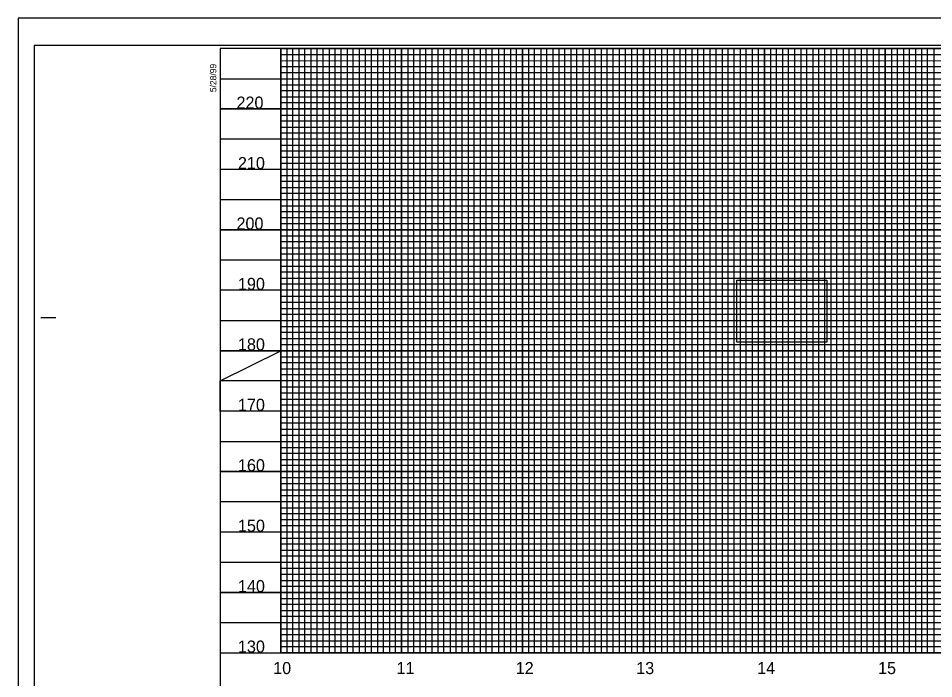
# Model space of a CAD drawing. Extents: x 1779926 to 1781610, y 620464 to 621564.
# Drawn here: x 1779926 to 1780683, y 621018 to 621564 of the extents above; entities that cross this region are included whole.
import ezdxf

# ---------------------------------------------------------------- set-up
doc = ezdxf.new("R2010")
doc.units = 0
for name, color, linetype in [('Exist Vertical Profile Horizontal Axis Label Major', 7, 'Continuous'), ('Exist Vertical Profile Vertical Axis Label', 7, 'Continuous'), ('Prop Grid Mask', 7, 'Continuous'), ('Scratch_Level_0', 7, 'Continuous'), ('Sheet Cutting Line CELL', 7, 'Continuous'), ('Sheet DOT Grid CELL', 7, 'Continuous'), ('Sheet Layout Profile Border Port 1', 7, 'Continuous'), ('Sheet Plot Border Inside CELL', 7, 'Continuous'), ('Sheet Plot Border Outside CELL', 7, 'Continuous'), ('Sheet Profile CELL', 7, 'Continuous'), ('Sheet Profile Grid Major CELL', 7, 'Continuous'), ('Sheet Profile Grid Middle CELL', 7, 'Continuous'), ('Sheet Profile Grid Minor CELL', 7, 'Continuous')]:
    doc.layers.add(name, color=color, linetype=linetype)

msp = doc.modelspace()

# ---------------------------------------------------------------- linework, layer by layer
at = {"layer": 'Prop Grid Mask'}
msp.add_lwpolyline([(1780520.24, 621347.48), (1780594.67, 621347.48), (1780594.67, 621296.16), (1780520.24, 621296.16)], close=True, dxfattribs=at)
at = {"layer": 'Scratch_Level_0'}
msp.add_lwpolyline([(1780142.96, 621039.18), (1780142.96, 621239.19), (1780092.96, 621239.19), (1780092.96, 621264.19), (1780142.96, 621289.19), (1780142.96, 621539.18), (1781392.96, 621539.18), (1781392.96, 621314.18), (1781542.96, 621314.18), (1781542.96, 621039.18)], close=True, dxfattribs=at)
at = {"layer": 'Sheet Cutting Line CELL'}
for p, q in [((1781609.96, 621564.19), (1779925.96, 621564.19)), ((1779925.96, 621564.19), (1779925.96, 620464.19))]:
    msp.add_line(p, q, dxfattribs=at)
at = {"layer": 'Sheet DOT Grid CELL'}
for p, q in [((1780142.96, 621039.19), (1780142.96, 621539.19)), ((1780192.96, 621039.19), (1780192.96, 621539.19)), ((1780242.96, 621039.19), (1780242.96, 621539.19)), ((1780292.96, 621039.19), (1780292.96, 621539.19)), ((1780342.96, 621039.19), (1780342.96, 621539.19)), ((1780392.96, 621039.19), (1780392.96, 621539.19)), ((1780442.96, 621039.19), (1780442.96, 621539.19)), ((1780492.96, 621039.19), (1780492.96, 621539.19)), ((1780542.96, 621039.19), (1780542.96, 621539.19)), ((1780592.96, 621039.19), (1780592.96, 621539.19)), ((1780642.96, 621039.19), (1780642.96, 621539.19)), ((1781392.91, 621489.19), (1780092.96, 621489.19)), ((1781392.91, 621439.19), (1780092.96, 621439.19)), ((1781392.96, 621389.19), (1780092.96, 621389.19)), ((1781392.91, 621339.19), (1780092.96, 621339.19)), ((1781592.96, 621289.19), (1780092.96, 621289.19)), ((1781592.96, 621239.19), (1780092.96, 621239.19)), ((1781592.96, 621189.19), (1780092.96, 621189.19)), ((1781592.96, 621139.19), (1780092.96, 621139.19)), ((1781592.96, 621089.19), (1780092.96, 621089.19))]:
    msp.add_line(p, q, dxfattribs=at)
at = {"layer": 'Sheet Layout Profile Border Port 1'}
msp.add_lwpolyline([(1780142.96, 621378.14), (1780142.96, 621039.19), (1781542.96, 621039.19), (1781542.96, 621314.19)], dxfattribs=at)
at = {"layer": 'Sheet Plot Border Inside CELL'}
msp.add_lwpolyline([(1779938.96, 620486.64), (1781605.46, 620486.64), (1781605.46, 621541.74), (1779938.96, 621541.74)], close=True, dxfattribs=at)
at = {"layer": 'Sheet Plot Border Outside CELL'}
msp.add_lwpolyline([(1779925.96, 620464.19), (1781609.96, 620464.19), (1781609.96, 621564.19), (1779925.96, 621564.19)], close=True, dxfattribs=at)
at = {"layer": 'Sheet Profile CELL'}
for p, q in [((1779944.46, 621316.69), (1779956.96, 621316.69)), ((1780092.96, 621039.19), (1781592.96, 621039.19))]:
    msp.add_line(p, q, dxfattribs=at)
msp.add_lwpolyline([(1781592.96, 621539.19), (1780092.96, 621539.19), (1780092.96, 620489.19), (1781592.96, 620489.19)], close=True, dxfattribs=at)
at = {"layer": 'Sheet Profile Grid Major CELL'}
for points in [[(1780142.96, 621539.19), (1780142.96, 621039.19), (1780192.96, 621039.19), (1780192.96, 621539.19), (1780242.96, 621539.19), (1780242.96, 621039.19), (1780292.96, 621039.19), (1780292.96, 621539.19), (1780342.96, 621539.19), (1780342.96, 621039.19), (1780392.96, 621039.19), (1780392.96, 621539.19), (1780442.96, 621539.19), (1780442.96, 621039.19), (1780492.96, 621039.19), (1780492.96, 621539.19), (1780542.96, 621539.19), (1780542.96, 621039.19), (1780592.96, 621039.19), (1780592.96, 621539.19), (1780642.96, 621539.19), (1780642.96, 621039.19), (1780692.96, 621039.19)], [(1780092.96, 621489.19), (1781392.96, 621489.19)], [(1781392.96, 621439.19), (1780092.96, 621439.19), (1780092.96, 621389.19), (1781392.96, 621389.19)], [(1781392.91, 621339.19), (1780092.96, 621339.19), (1780092.96, 621289.19), (1781592.96, 621289.19)], [(1781592.96, 621239.19), (1780092.96, 621239.19), (1780092.96, 621189.19), (1781592.96, 621189.19)], [(1781592.96, 621139.19), (1780092.96, 621139.19), (1780092.96, 621139.19), (1780092.96, 621089.19), (1781592.96, 621089.19)]]:
    msp.add_lwpolyline(points, dxfattribs=at)
at = {"layer": 'Sheet Profile Grid Middle CELL'}
msp.add_line((1780092.96, 621514.19), (1781392.91, 621514.19), dxfattribs=at)
for points in [[(1780167.96, 621539.19), (1780167.96, 621039.19), (1780217.96, 621039.19), (1780217.96, 621539.19), (1780267.96, 621539.19), (1780267.96, 621039.19), (1780317.96, 621039.19), (1780317.96, 621539.19), (1780367.96, 621539.19), (1780367.96, 621039.19), (1780417.96, 621039.19), (1780417.96, 621539.19), (1780467.96, 621539.19), (1780467.96, 621039.19), (1780517.96, 621039.19), (1780517.96, 621539.19), (1780567.96, 621539.19), (1780567.96, 621039.19), (1780617.96, 621039.19), (1780617.96, 621539.19), (1780667.96, 621539.19), (1780667.96, 621039.19), (1780717.96, 621039.19)], [(1781392.96, 621464.19), (1780092.96, 621464.19), (1780092.96, 621414.19), (1781392.96, 621414.19)], [(1781392.91, 621364.19), (1780092.96, 621364.19), (1780092.96, 621314.19), (1781417.96, 621314.19)], [(1781592.96, 621264.19), (1780092.96, 621264.19), (1780092.96, 621214.19), (1781592.96, 621214.19)], [(1781592.96, 621164.19), (1780092.96, 621164.19), (1780092.96, 621114.19), (1781592.96, 621114.19)], [(1781592.96, 621064.19), (1780092.96, 621064.19)]]:
    msp.add_lwpolyline(points, dxfattribs=at)
at = {"layer": 'Sheet Profile Grid Minor CELL'}
for p, q in [((1780142.96, 621534.19), (1781392.96, 621534.19)), ((1780142.96, 621529.19), (1780142.96, 621529.19)), ((1781392.96, 621529.19), (1780142.96, 621528.84)), ((1780142.96, 621524.19), (1781392.96, 621524.19)), ((1781392.91, 621404.19), (1780142.96, 621404.19)), ((1781392.96, 621399.19), (1780142.96, 621399.19)), ((1781392.96, 621394.19), (1780142.96, 621394.19)), ((1780142.96, 621384.19), (1781392.96, 621384.19)), ((1781392.96, 621379.19), (1780142.96, 621379.19)), ((1780142.96, 621374.19), (1781392.96, 621374.19)), ((1781392.96, 621354.19), (1780142.96, 621354.19)), ((1780142.96, 621349.19), (1781392.96, 621349.19)), ((1781392.91, 621329.19), (1780142.96, 621329.19)), ((1780142.96, 621324.19), (1781392.91, 621324.19)), ((1781542.96, 621304.19), (1780142.96, 621304.19)), ((1780142.96, 621299.19), (1781542.96, 621299.19)), ((1781542.96, 621294.19), (1780142.96, 621294.19)), ((1780142.96, 621284.19), (1781542.96, 621284.19)), ((1781542.96, 621279.19), (1780142.96, 621279.19)), ((1780142.96, 621274.19), (1781542.96, 621274.19)), ((1781542.96, 621269.19), (1780142.96, 621269.19)), ((1780142.96, 621259.19), (1781542.96, 621259.19)), ((1781542.96, 621254.19), (1780142.96, 621254.19)), ((1780142.96, 621249.19), (1781542.96, 621249.19)), ((1781542.96, 621244.19), (1780142.96, 621244.19)), ((1780142.96, 621234.19), (1781542.96, 621234.19)), ((1781542.96, 621229.19), (1780142.96, 621229.19)), ((1780142.96, 621224.19), (1781542.96, 621224.19)), ((1781542.96, 621219.19), (1780142.96, 621219.19)), ((1780142.96, 621209.19), (1781542.96, 621209.19)), ((1781542.96, 621204.19), (1780142.96, 621204.19)), ((1780142.96, 621199.19), (1781542.96, 621199.19)), ((1781542.96, 621194.19), (1780142.96, 621194.19)), ((1780142.96, 621184.19), (1781542.96, 621184.19)), ((1781542.96, 621179.19), (1780142.96, 621179.19)), ((1780142.96, 621174.19), (1781542.96, 621174.19)), ((1781542.96, 621169.19), (1780142.96, 621169.19)), ((1780142.96, 621159.19), (1781542.96, 621159.19)), ((1781542.96, 621154.19), (1780142.96, 621154.19)), ((1781542.96, 621149.19), (1780142.96, 621149.19)), ((1781542.96, 621144.19), (1780142.96, 621144.19)), ((1780142.96, 621134.19), (1781542.96, 621134.19)), ((1781542.96, 621129.19), (1780142.96, 621129.19)), ((1780142.96, 621124.19), (1781542.96, 621124.19)), ((1781542.96, 621119.19), (1780142.96, 621119.19)), ((1780142.96, 621109.19), (1781542.96, 621109.19)), ((1781542.96, 621104.19), (1780142.96, 621104.19)), ((1780142.96, 621099.19), (1781542.96, 621099.19)), ((1781542.96, 621094.19), (1780142.96, 621094.19)), ((1780142.96, 621084.19), (1781542.96, 621084.19)), ((1781542.96, 621079.19), (1780142.96, 621079.19)), ((1780142.96, 621074.19), (1781542.96, 621074.19)), ((1781542.96, 621069.19), (1780142.96, 621069.19)), ((1780142.96, 621059.19), (1781542.96, 621059.19)), ((1781542.96, 621054.19), (1780142.96, 621054.19)), ((1780142.96, 621049.19), (1781542.96, 621049.19))]:
    msp.add_line(p, q, dxfattribs=at)
for points in [[(1780147.96, 621539.19), (1780147.96, 621039.19), (1780152.96, 621039.19), (1780152.96, 621539.19), (1780157.96, 621539.19), (1780157.96, 621039.19), (1780162.96, 621039.19), (1780162.96, 621539.19), (1780172.96, 621539.19), (1780172.96, 621039.19), (1780177.96, 621039.19), (1780177.96, 621539.19), (1780182.96, 621539.19), (1780182.96, 621039.19), (1780187.96, 621039.19), (1780197.96, 621039.19), (1780202.96, 621039.19), (1780202.96, 621539.19), (1780207.96, 621539.19), (1780207.96, 621039.19), (1780212.96, 621039.19), (1780212.96, 621539.19), (1780222.96, 621539.19), (1780222.96, 621039.19), (1780227.96, 621039.19), (1780227.96, 621539.19), (1780232.96, 621539.19), (1780232.96, 621039.19), (1780237.96, 621039.19), (1780237.96, 621539.19), (1780247.96, 621539.19), (1780247.96, 621039.19), (1780252.96, 621039.19), (1780252.96, 621539.19), (1780257.96, 621539.19), (1780257.96, 621039.19), (1780262.96, 621039.19), (1780262.96, 621539.19), (1780272.96, 621539.19), (1780272.96, 621039.19), (1780277.96, 621039.19), (1780277.96, 621539.19), (1780282.96, 621539.19), (1780282.96, 621039.19), (1780287.96, 621039.19), (1780287.96, 621539.19), (1780297.96, 621539.19), (1780297.96, 621039.19), (1780302.96, 621039.19), (1780302.96, 621539.19), (1780307.96, 621539.19), (1780307.96, 621039.19), (1780312.96, 621039.19), (1780312.96, 621539.19), (1780322.96, 621539.19), (1780322.96, 621039.19), (1780327.96, 621039.19), (1780327.96, 621539.19), (1780332.96, 621539.19), (1780332.96, 621039.19), (1780337.96, 621039.19), (1780337.96, 621539.19), (1780347.96, 621539.19), (1780347.96, 621039.19), (1780352.96, 621039.19), (1780352.96, 621539.19), (1780357.96, 621539.19), (1780357.96, 621039.19)], [(1780187.96, 621039.19), (1780187.96, 621539.19), (1780197.96, 621539.19), (1780197.96, 621039.19)], [(1780357.96, 621039.19), (1780362.96, 621039.19), (1780362.96, 621539.19), (1780372.96, 621539.19), (1780372.96, 621039.19), (1780377.96, 621039.19), (1780377.96, 621539.19), (1780382.96, 621539.19), (1780382.96, 621039.19), (1780387.96, 621039.19), (1780387.96, 621539.19), (1780397.96, 621539.19), (1780397.96, 621039.19), (1780402.96, 621039.19), (1780402.96, 621539.19), (1780407.96, 621539.19), (1780407.96, 621039.19), (1780412.96, 621039.19), (1780412.96, 621539.19), (1780422.96, 621539.19), (1780422.96, 621039.19), (1780427.96, 621039.19), (1780427.96, 621539.19), (1780432.96, 621539.19), (1780432.96, 621039.19), (1780437.96, 621039.19), (1780437.96, 621539.19), (1780447.96, 621539.19), (1780447.96, 621039.19), (1780452.96, 621039.19), (1780452.96, 621539.19), (1780457.96, 621539.19), (1780457.96, 621039.19), (1780462.96, 621039.19), (1780462.96, 621539.19), (1780472.96, 621539.19), (1780472.96, 621039.19), (1780477.96, 621039.19), (1780477.96, 621539.19), (1780482.96, 621539.19), (1780482.96, 621039.19), (1780487.96, 621039.19), (1780487.96, 621539.19), (1780497.96, 621539.19), (1780497.96, 621039.19), (1780502.96, 621039.19), (1780502.96, 621539.19), (1780507.96, 621539.19), (1780507.96, 621039.19), (1780512.96, 621039.19), (1780512.96, 621539.19), (1780522.96, 621539.19), (1780522.96, 621039.19), (1780527.96, 621039.19), (1780527.96, 621539.19), (1780532.96, 621539.19), (1780532.96, 621039.19), (1780537.96, 621039.19), (1780537.96, 621539.19), (1780547.96, 621539.19), (1780547.96, 621039.19), (1780552.96, 621039.19), (1780552.96, 621539.19), (1780557.96, 621539.19), (1780557.96, 621039.19), (1780562.96, 621039.19), (1780562.96, 621539.19), (1780572.96, 621539.19), (1780572.96, 621039.19), (1780577.96, 621039.19), (1780577.96, 621539.19), (1780582.96, 621539.19), (1780582.96, 621039.19), (1780587.96, 621039.19), (1780587.96, 621539.19), (1780597.96, 621539.19), (1780597.96, 621039.19), (1780602.96, 621039.19), (1780602.96, 621539.19), (1780607.96, 621539.19), (1780607.96, 621039.19), (1780612.96, 621039.19), (1780612.96, 621539.19), (1780622.96, 621539.19), (1780622.96, 621039.19), (1780627.96, 621039.19), (1780627.96, 621539.19), (1780632.96, 621539.19), (1780632.96, 621039.19), (1780637.96, 621039.19), (1780637.96, 621539.19), (1780647.96, 621539.19), (1780647.96, 621039.19), (1780652.96, 621039.19), (1780652.96, 621539.19), (1780657.96, 621539.19), (1780657.96, 621039.19), (1780662.96, 621039.19), (1780662.96, 621539.19), (1780672.96, 621539.19)], [(1780672.96, 621539.19), (1780672.96, 621039.19), (1780677.96, 621039.19), (1780677.96, 621539.19), (1780682.96, 621539.19), (1780682.96, 621039.19), (1780687.96, 621039.19)], [(1781392.96, 621519.19), (1780142.96, 621519.19), (1780142.96, 621509.19), (1781392.96, 621509.19)], [(1781392.91, 621504.19), (1780142.96, 621504.19), (1780142.96, 621499.19), (1781392.96, 621499.19)], [(1781392.96, 621494.19), (1780142.96, 621494.19), (1780142.96, 621484.19), (1781392.96, 621484.19)], [(1781392.96, 621479.19), (1780142.96, 621479.19), (1780142.96, 621474.19), (1781392.96, 621474.19)], [(1781392.96, 621469.19), (1780142.96, 621469.19), (1780142.96, 621459.19), (1781392.96, 621459.19)], [(1781392.96, 621454.19), (1780142.96, 621454.19), (1780142.96, 621449.19), (1781392.96, 621449.19)], [(1781392.96, 621444.19), (1780142.96, 621444.19), (1780142.96, 621434.19), (1781392.96, 621434.19)], [(1781392.96, 621429.09), (1780143.06, 621429.09), (1780143.06, 621424.19), (1781392.96, 621424.19)], [(1781392.96, 621419.19), (1780142.96, 621419.19), (1780142.96, 621409.19), (1781392.96, 621409.19)], [(1781392.91, 621369.19), (1780142.96, 621369.19), (1780142.96, 621359.19), (1781392.91, 621359.19)], [(1781392.91, 621344.19), (1780142.96, 621344.19), (1780142.96, 621334.19), (1781392.91, 621334.19)], [(1781392.91, 621319.19), (1780142.96, 621319.19), (1780142.96, 621309.19), (1781542.96, 621309.19)], [(1781542.96, 621044.19), (1780142.96, 621044.19)]]:
    msp.add_lwpolyline(points, dxfattribs=at)

# ---------------------------------------------------------------- texts
at = {"layer": 'Exist Vertical Profile Horizontal Axis Label Major'}
for s, p in [('10', (1780136.73, 621021.68)), ('11', (1780238.7, 621021.69)), ('12', (1780337.27, 621021.69)), ('13', (1780436.95, 621021.69)), ('14', (1780537, 621021.69)), ('15', (1780636.93, 621021.69))]:
    msp.add_text(s, height=10, dxfattribs=at).set_placement(p)
at = {"layer": 'Exist Vertical Profile Vertical Axis Label'}
for s, p in [('220', (1780106.39, 621489.44)), ('210', (1780107.59, 621439.44)), ('200', (1780106.39, 621389.44)), ('190', (1780107.59, 621339.44)), ('180', (1780107.59, 621289.44)), ('170', (1780107.59, 621239.44)), ('160', (1780107.59, 621189.44)), ('150', (1780107.59, 621139.44)), ('140', (1780107.59, 621089.44)), ('130', (1780107.59, 621039.44))]:
    msp.add_text(s, height=10, dxfattribs=at).set_placement(p)
at = {"layer": 'Sheet Profile CELL'}
msp.add_text('5/28/99', height=5.25, rotation=90, dxfattribs=at).set_placement((1780089.72, 621503.1))

doc.saveas('drawing.dxf')
